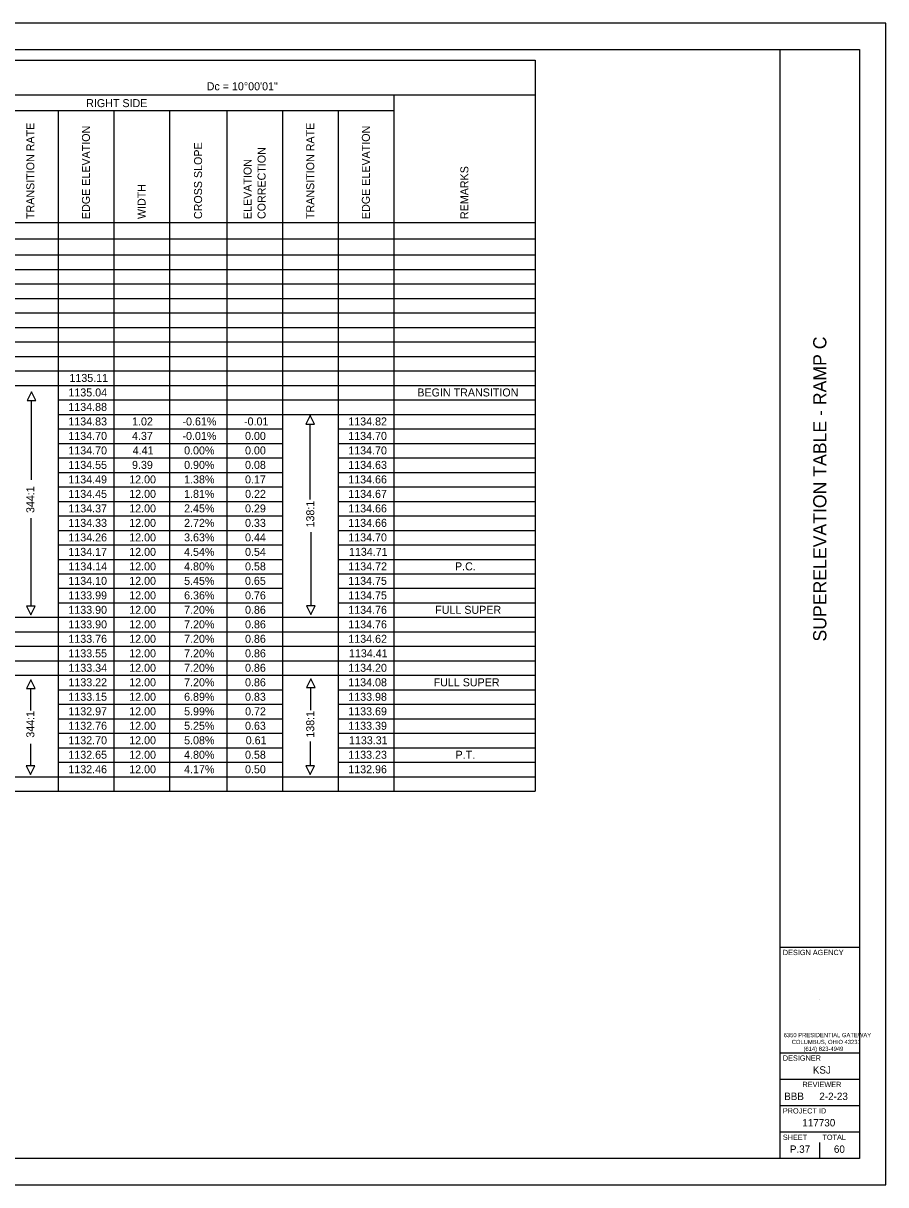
# Model space of a CAD drawing. Extents: x 0 to 34, y 0 to 22.
# Drawn here: x 17.66 to 34, y 0 to 22 of the extents above; entities that cross this region are included whole.
import ezdxf

# ---------------------------------------------------------------- set-up
doc = ezdxf.new("R2010")
doc.units = 0
for name, color, linetype in [('SH_Border', 7, 'Continuous'), ('SH_Cut_Line', 7, 'Continuous'), ('SH_Data', 7, 'Continuous'), ('SH_Text', 7, 'Continuous')]:
    doc.layers.add(name, color=color, linetype=linetype)

msp = doc.modelspace()

# ---------------------------------------------------------------- linework, layer by layer
at = {"layer": 'SH_Border'}
for p, q in [((32, 0.5), (32, 21.5)), ((32, 4.5), (33.5, 4.5)), ((32, 2.5), (33.5, 2.5)), ((32, 2), (33.5, 2)), ((32, 1.5), (33.5, 1.5)), ((32, 1), (33.5, 1))]:
    msp.add_line(p, q, dxfattribs=at)
msp.add_lwpolyline([(1.5, 21.5), (33.5, 21.5), (33.5, 0.5), (1.5, 0.5)], close=True, dxfattribs=at)
at = {"layer": 'SH_Cut_Line'}
msp.add_lwpolyline([(0, 0), (34, 0), (34, 22), (0, 22)], close=True, dxfattribs=at)
at = {"layer": 'SH_Data'}
for p, q in [((32.75, 3.5), (32.75, 3.5)), ((32.375, 0.675), (32.375, 0.675)), ((32.75, 0.5), (32.75, 0.8))]:
    msp.add_line(p, q, dxfattribs=at)
at = {"layer": 'SH_Text'}
for p, q in [((6.177, 21.3), (27.356, 21.3)), ((27.356, 21.3), (27.356, 7.454)), ((6.177, 20.641), (27.356, 20.641)), ((24.677, 20.641), (24.677, 7.454)), ((6.177, 20.345), (24.677, 20.345)), ((18.32, 20.345), (18.32, 18.225)), ((19.374, 20.345), (19.374, 18.225)), ((20.428, 20.345), (20.428, 18.225)), ((21.515, 20.345), (21.515, 18.225)), ((22.569, 20.345), (22.569, 18.225)), ((23.623, 20.345), (23.623, 18.225)), ((6.177, 18.225), (27.356, 18.225)), ((18.32, 18.225), (18.32, 7.454)), ((19.374, 18.225), (19.374, 7.454)), ((20.428, 18.225), (20.428, 7.454)), ((21.515, 18.225), (21.515, 7.454)), ((22.569, 18.225), (22.569, 7.454)), ((23.623, 18.225), (23.623, 7.454)), ((6.177, 17.918), (27.356, 17.918)), ((6.177, 17.611), (27.356, 17.611)), ((6.177, 17.336), (27.356, 17.336)), ((6.177, 17.062), (27.356, 17.062)), ((6.177, 16.787), (27.356, 16.787)), ((6.177, 16.513), (27.356, 16.513)), ((6.177, 16.238), (27.356, 16.238)), ((6.177, 15.964), (27.356, 15.964)), ((6.177, 15.689), (27.356, 15.689)), ((6.177, 15.415), (27.356, 15.415)), ((6.177, 15.14), (27.356, 15.14)), ((17.815, 13.35), (17.815, 14.855)), ((18.32, 14.865), (27.356, 14.865)), ((18.32, 14.591), (27.356, 14.591)), ((18.32, 14.316), (22.569, 14.316)), ((23.096, 12.977), (23.096, 14.404)), ((23.623, 14.316), (27.356, 14.316)), ((18.32, 14.042), (22.569, 14.042)), ((23.623, 14.042), (27.356, 14.042)), ((18.32, 13.767), (22.569, 13.767)), ((23.623, 13.767), (27.356, 13.767)), ((18.32, 13.493), (22.569, 13.493)), ((23.623, 13.493), (27.356, 13.493)), ((18.32, 13.218), (22.569, 13.218)), ((23.623, 13.218), (27.356, 13.218)), ((18.32, 12.944), (22.569, 12.944)), ((23.623, 12.944), (27.356, 12.944)), ((17.804, 12.625), (17.804, 10.956)), ((18.32, 12.669), (22.569, 12.669)), ((23.623, 12.669), (27.356, 12.669)), ((18.32, 12.395), (22.569, 12.395)), ((23.107, 12.362), (23.107, 10.967)), ((23.623, 12.395), (27.356, 12.395)), ((18.32, 12.12), (22.569, 12.12)), ((23.623, 12.12), (27.356, 12.12)), ((18.32, 11.846), (22.569, 11.846)), ((23.623, 11.846), (27.356, 11.846)), ((18.32, 11.571), (22.569, 11.571)), ((23.623, 11.571), (27.356, 11.571)), ((18.32, 11.297), (22.569, 11.297)), ((23.623, 11.297), (27.356, 11.297)), ((18.32, 11.022), (22.569, 11.022)), ((23.623, 11.022), (27.356, 11.022)), ((6.177, 10.748), (27.356, 10.748)), ((6.177, 10.473), (27.356, 10.473)), ((6.177, 10.199), (27.356, 10.199)), ((6.177, 9.924), (27.356, 9.924)), ((6.177, 9.65), (27.356, 9.65)), ((17.804, 8.98), (17.804, 9.397)), ((18.32, 9.375), (22.569, 9.375)), ((23.107, 8.991), (23.107, 9.419)), ((23.623, 9.375), (27.356, 9.375)), ((18.32, 9.101), (22.569, 9.101)), ((23.623, 9.101), (27.356, 9.101)), ((18.32, 8.826), (22.569, 8.826)), ((23.623, 8.826), (27.356, 8.826)), ((18.32, 8.552), (22.569, 8.552)), ((23.096, 8.398), (23.096, 7.937)), ((23.623, 8.552), (27.356, 8.552)), ((17.798, 8.354), (17.798, 7.937)), ((18.32, 8.277), (22.569, 8.277)), ((23.623, 8.277), (27.356, 8.277)), ((18.32, 8.003), (22.569, 8.003)), ((23.623, 8.003), (27.356, 8.003)), ((6.177, 7.728), (27.356, 7.728)), ((6.177, 7.454), (27.356, 7.454))]:
    msp.add_line(p, q, dxfattribs=at)
for points in [[(17.815, 15.019), (17.733, 14.855), (17.897, 14.855)], [(23.096, 14.569), (23.014, 14.404), (23.178, 14.404)], [(17.804, 10.792), (17.886, 10.956), (17.722, 10.956)], [(23.107, 10.803), (23.189, 10.967), (23.025, 10.967)], [(17.804, 9.562), (17.722, 9.397), (17.886, 9.397)], [(23.107, 9.584), (23.025, 9.419), (23.189, 9.419)], [(17.798, 7.772), (17.88, 7.937), (17.715, 7.937)], [(23.096, 7.772), (23.178, 7.937), (23.014, 7.937)]]:
    msp.add_lwpolyline(points, close=True, dxfattribs=at)

# ---------------------------------------------------------------- texts
at = {"layer": 'SH_Data'}
msp.add_text('SUPERELEVATION TABLE - RAMP C', height=0.25, rotation=90, dxfattribs=at).set_placement((32.875, 10.289))
for s, height, p in [('DESIGN AGENCY', 0.1, (32.05, 4.35)), ('6350 PRESIDENTIAL GATEWAY', 0.08, (32.065, 2.795)), ('COLUMBUS, OHIO 43231', 0.08, (32.218, 2.665)), ('DESIGNER', 0.1, (32.05, 2.35)), ('(614) 823-4949', 0.08, (32.441, 2.535)), ('KSJ', 0.14, (32.617, 2.105)), ('REVIEWER', 0.1, (32.422, 1.85)), ('BBB', 0.14, (32.075, 1.605)), ('2-2-23', 0.14, (32.741, 1.605)), ('PROJECT ID', 0.1, (32.05, 1.35)), ('117730', 0.14, (32.419, 1.105)), ('SHEET', 0.1, (32.05, 0.85)), ('TOTAL', 0.1, (32.8, 0.85)), ('P.37', 0.14, (32.183, 0.605)), ('60', 0.14, (33.017, 0.605))]:
    msp.add_text(s, height=height, dxfattribs=at).set_placement(p)
at = {"layer": 'SH_Text'}
for s, height, p in [('Dc = 10°00\'01"', 0.15153, (21.135, 20.73)), ('RIGHT SIDE', 0.1515, (18.852, 20.411)), ('1135.11', 0.1515, (18.534, 15.206)), ('1135.04', 0.1515, (18.515, 14.931)), ('BEGIN TRANSITION', 0.15153, (25.126, 14.931)), ('1134.88', 0.1515, (18.514, 14.657)), ('1134.83', 0.1515, (18.514, 14.382)), ('1.02', 0.1515, (19.721, 14.382)), ('-0.61%', 0.1515, (20.676, 14.382)), ('-0.01', 0.1515, (21.842, 14.382)), ('1134.82', 0.1515, (23.818, 14.382)), ('1134.70', 0.1515, (18.514, 14.108)), ('4.37', 0.1515, (19.72, 14.108)), ('-0.01%', 0.1515, (20.676, 14.108)), ('0.00', 0.1515, (21.861, 14.108)), ('1134.70', 0.1515, (23.817, 14.108)), ('1134.70', 0.1515, (18.514, 13.833)), ('4.41', 0.1515, (19.733, 13.833)), ('0.00%', 0.1515, (20.707, 13.833)), ('0.00', 0.1515, (21.861, 13.833)), ('1134.70', 0.1515, (23.817, 13.833)), ('1134.55', 0.1515, (18.514, 13.559)), ('9.39', 0.1515, (19.72, 13.559)), ('0.90%', 0.1515, (20.707, 13.559)), ('0.08', 0.1515, (21.861, 13.559)), ('1134.63', 0.1515, (23.817, 13.559)), ('1134.49', 0.1515, (18.514, 13.284)), ('12.00', 0.1515, (19.667, 13.284)), ('1.38%', 0.1515, (20.707, 13.284)), ('0.17', 0.1515, (21.861, 13.284)), ('1134.66', 0.1515, (23.817, 13.284)), ('1134.45', 0.1515, (18.514, 13.01)), ('12.00', 0.1515, (19.667, 13.01)), ('1.81%', 0.1515, (20.707, 13.01)), ('0.22', 0.1515, (21.862, 13.01)), ('1134.67', 0.1515, (23.817, 13.01)), ('1134.37', 0.1515, (18.514, 12.735)), ('12.00', 0.1515, (19.667, 12.735)), ('2.45%', 0.1515, (20.707, 12.735)), ('0.29', 0.1515, (21.861, 12.735)), ('1134.66', 0.1515, (23.817, 12.735)), ('1134.33', 0.1515, (18.514, 12.461)), ('12.00', 0.1515, (19.667, 12.461)), ('2.72%', 0.1515, (20.707, 12.461)), ('0.33', 0.1515, (21.861, 12.461)), ('1134.66', 0.1515, (23.817, 12.461)), ('1134.26', 0.1515, (18.514, 12.186)), ('12.00', 0.1515, (19.667, 12.186)), ('3.63%', 0.1515, (20.707, 12.186)), ('0.44', 0.1515, (21.861, 12.186)), ('1134.70', 0.1515, (23.817, 12.186)), ('1134.17', 0.1515, (18.514, 11.912)), ('12.00', 0.1515, (19.667, 11.912)), ('4.54%', 0.1515, (20.707, 11.912)), ('0.54', 0.1515, (21.861, 11.912)), ('1134.71', 0.1515, (23.83, 11.912)), ('1134.14', 0.1515, (18.515, 11.637)), ('12.00', 0.1515, (19.667, 11.637)), ('4.80%', 0.1515, (20.707, 11.637)), ('0.58', 0.1515, (21.861, 11.637)), ('1134.72', 0.1515, (23.818, 11.637)), ('P.C.', 0.1515, (25.839, 11.637)), ('1134.10', 0.1515, (18.514, 11.363)), ('12.00', 0.1515, (19.667, 11.363)), ('5.45%', 0.1515, (20.707, 11.363)), ('0.65', 0.1515, (21.86, 11.363)), ('1134.75', 0.1515, (23.817, 11.363)), ('1133.99', 0.1515, (18.514, 11.088)), ('12.00', 0.1515, (19.667, 11.088)), ('6.36%', 0.1515, (20.707, 11.088)), ('0.76', 0.1515, (21.861, 11.088)), ('1134.75', 0.1515, (23.817, 11.088)), ('1133.90', 0.1515, (18.514, 10.814)), ('12.00', 0.1515, (19.667, 10.814)), ('7.20%', 0.1515, (20.707, 10.814)), ('0.86', 0.1515, (21.861, 10.814)), ('1134.76', 0.1515, (23.817, 10.814)), (' FULL SUPER', 0.15153, (25.407, 10.814)), ('1133.90', 0.1515, (18.514, 10.539)), ('12.00', 0.1515, (19.667, 10.539)), ('7.20%', 0.1515, (20.707, 10.539)), ('0.86', 0.1515, (21.861, 10.539)), ('1134.76', 0.1515, (23.817, 10.539)), ('1133.76', 0.1515, (18.514, 10.265)), ('12.00', 0.1515, (19.667, 10.265)), ('7.20%', 0.1515, (20.707, 10.265)), ('0.86', 0.1515, (21.861, 10.265)), ('1134.62', 0.1515, (23.818, 10.265)), ('1133.55', 0.1515, (18.514, 9.99)), ('12.00', 0.1515, (19.667, 9.99)), ('7.20%', 0.1515, (20.707, 9.99)), ('0.86', 0.1515, (21.861, 9.99)), ('1134.41', 0.1515, (23.83, 9.99)), ('1133.34', 0.1515, (18.515, 9.716)), ('12.00', 0.1515, (19.667, 9.716)), ('7.20%', 0.1515, (20.707, 9.716)), ('0.86', 0.1515, (21.861, 9.716)), ('1134.20', 0.1515, (23.817, 9.716)), ('1133.22', 0.1515, (18.515, 9.441)), ('12.00', 0.1515, (19.667, 9.441)), ('7.20%', 0.1515, (20.707, 9.441)), ('0.86', 0.1515, (21.861, 9.441)), ('1134.08', 0.1515, (23.817, 9.441)), ('FULL SUPER', 0.1515, (25.434, 9.441)), ('1133.15', 0.1515, (18.514, 9.167)), ('12.00', 0.1515, (19.667, 9.167)), ('6.89%', 0.1515, (20.707, 9.167)), ('0.83', 0.1515, (21.861, 9.167)), ('1133.98', 0.1515, (23.817, 9.167)), ('1132.97', 0.1515, (18.514, 8.892)), ('12.00', 0.1515, (19.667, 8.892)), ('5.99%', 0.1515, (20.707, 8.892)), ('0.72', 0.1515, (21.862, 8.892)), ('1133.69', 0.1515, (23.817, 8.892)), ('1132.76', 0.1515, (18.514, 8.618)), ('12.00', 0.1515, (19.667, 8.618)), ('5.25%', 0.1515, (20.707, 8.618)), ('0.63', 0.1515, (21.861, 8.618)), ('1133.39', 0.1515, (23.817, 8.618)), ('1132.70', 0.1515, (18.514, 8.343)), ('12.00', 0.1515, (19.667, 8.343)), ('5.08%', 0.1515, (20.707, 8.343)), ('0.61', 0.1515, (21.874, 8.343)), ('1133.31', 0.1515, (23.83, 8.343)), ('1132.65', 0.1515, (18.514, 8.069)), ('12.00', 0.1515, (19.667, 8.069)), ('4.80%', 0.1515, (20.707, 8.069)), ('0.58', 0.1515, (21.861, 8.069)), ('1133.23', 0.1515, (23.817, 8.069)), ('P.T.', 0.1515, (25.85, 8.069)), ('1132.46', 0.1515, (18.514, 7.794)), ('12.00', 0.1515, (19.667, 7.794)), ('4.17%', 0.1515, (20.707, 7.794)), ('0.50', 0.1515, (21.861, 7.794)), ('1132.96', 0.1515, (23.817, 7.794))]:
    msp.add_text(s, height=height, dxfattribs=at).set_placement(p)
for s, height, p in [('TRANSITION RATE', 0.15151, (17.869, 18.291)), ('EDGE ELEVATION', 0.15151, (18.923, 18.291)), ('TRANSITION RATE', 0.15151, (23.172, 18.291)), ('EDGE ELEVATION', 0.15151, (24.226, 18.291)), ('CROSS SLOPE', 0.15151, (21.047, 18.291)), ('CORRECTION', 0.1515, (22.25, 18.291)), ('ELEVATION ', 0.1515, (21.985, 18.291)), ('REMARKS', 0.1515, (26.092, 18.291)), ('WIDTH', 0.1515, (19.977, 18.291)), ('344:1', 0.1515, (17.869, 12.723)), ('138:1', 0.1515, (23.172, 12.449)), ('344:1', 0.1515, (17.869, 8.468)), ('138:1', 0.1515, (23.172, 8.468))]:
    msp.add_text(s, height=height, rotation=90, dxfattribs=at).set_placement(p)

doc.saveas('drawing.dxf')
